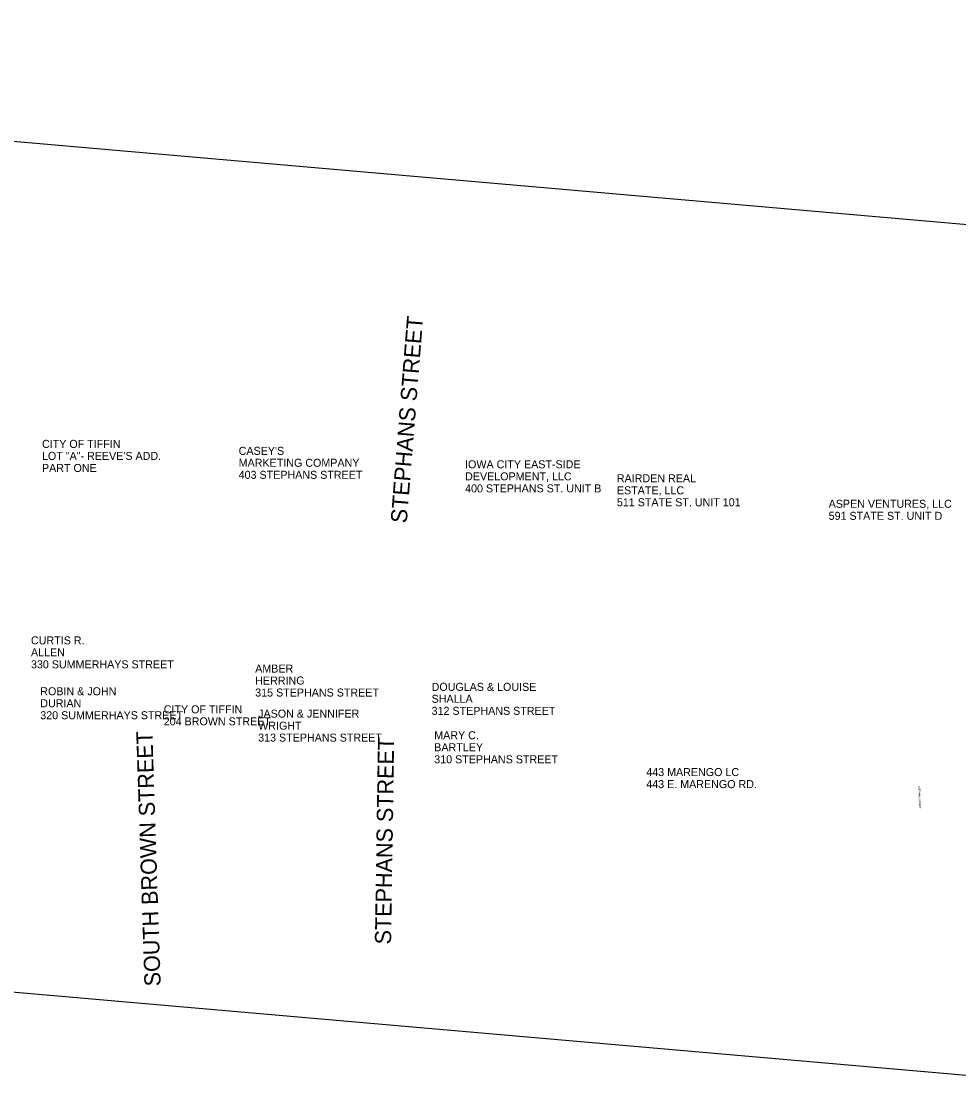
# Model space of a CAD drawing. Extents: x 20499598 to 20505777, y 7953097 to 7954577.
# Drawn here: x 20501318 to 20502423, y 7953308 to 7954577 of the extents above; entities that cross this region are included whole.
import ezdxf

# ---------------------------------------------------------------- set-up
doc = ezdxf.new("R2010")
doc.units = 0
for name, color, linetype in [('Default', 7, 'Continuous'), ('DisROW Property Lines', 7, 'Continuous'), ('NamedBoundary', 7, 'Continuous'), ('Text', 7, 'Continuous')]:
    doc.layers.add(name, color=color, linetype=linetype)

msp = doc.modelspace()

# ---------------------------------------------------------------- linework, layer by layer
at = {"layer": 'NamedBoundary'}
msp.add_lwpolyline([(20499685.1, 7954577.3), (20499598.1, 7953581.1), (20502721.2, 7953308.4), (20502808.2, 7954304.6)], close=True, dxfattribs=at)

# ---------------------------------------------------------------- texts
at = {"layer": 'Default'}
for p in [(20502376, 7953675), (20502376, 7953674.9)]:
    msp.add_text('STEPHANS STREET', height=2, rotation=271.5172, dxfattribs=at).set_placement(p)
at = {"layer": 'DisROW Property Lines'}
for s, height, p in [('CITY OF TIFFIN', 9.449, (20501341.8, 7954074)), ('LOT "A"- REEVE\'S ADD.', 9.449, (20501341.8, 7954059.8)), ("CASEY'S", 9.45, (20501573.9, 7954065.8)), ('PART ONE', 9.45, (20501341.8, 7954045.6)), ('MARKETING COMPANY', 9.449, (20501573.9, 7954051.7)), ('IOWA CITY EAST-SIDE', 9.449, (20501841.1, 7954049.9)), ('403 STEPHANS STREET', 9.449, (20501573.9, 7954037.5)), ('DEVELOPMENT, LLC', 9.449, (20501841.1, 7954035.7)), ('RAIRDEN REAL ', 9.449, (20502020.2, 7954033.4)), ('400 STEPHANS ST. UNIT B', 9.449, (20501841.1, 7954021.5)), ('ESTATE, LLC', 9.449, (20502020.2, 7954019.2)), ('511 STATE ST. UNIT 101', 9.449, (20502020.2, 7954005.1)), ('ASPEN VENTURES, LLC', 9.449, (20502270.1, 7954003.3)), ('591 STATE ST. UNIT D', 9.449, (20502270.1, 7953989.1)), ('CURTIS R.', 9.45, (20501328.8, 7953842.1)), ('ALLEN', 9.45, (20501328.8, 7953827.9)), ('330 SUMMERHAYS STREET', 9.449, (20501328.8, 7953813.8)), ('AMBER', 9.45, (20501593.4, 7953808.8)), ('HERRING', 9.45, (20501593.4, 7953794.7)), ('ROBIN & JOHN', 9.449, (20501339.8, 7953782)), ('315 STEPHANS STREET', 9.449, (20501593.4, 7953780.5)), ('DOUGLAS & LOUISE', 9.449, (20501801.6, 7953787.2)), ('DURIAN', 9.45, (20501339.8, 7953767.8)), ('SHALLA', 9.45, (20501801.6, 7953773.1)), ('320 SUMMERHAYS STREET', 9.449, (20501339.8, 7953753.7)), ('CITY OF TIFFIN', 9.449, (20501485.5, 7953760.7)), ('JASON & JENNIFER', 9.449, (20501596.9, 7953755.6)), ('312 STEPHANS STREET', 9.449, (20501801.6, 7953758.9)), ('204 BROWN STREET', 9.449, (20501485.5, 7953746.5)), ('WRIGHT', 9.45, (20501596.9, 7953741.4)), ('313 STEPHANS STREET', 9.449, (20501596.9, 7953727.3)), ('MARY C.', 9.45, (20501804.7, 7953730.1)), ('BARTLEY', 9.45, (20501804.7, 7953715.9)), ('310 STEPHANS STREET', 9.449, (20501804.7, 7953701.7)), ('443 MARENGO LC', 9.449, (20502054.9, 7953686.6)), ('443 E. MARENGO RD.', 9.449, (20502054.9, 7953672.4))]:
    msp.add_text(s, height=height, dxfattribs=at).set_placement(p)
at = {"layer": 'Text'}
for s, rotation, p in [('STEPHANS STREET', 85.4303, (20501772.2, 7953984.6)), ('SOUTH BROWN STREET', 91.8771, (20501481.9, 7953438.7)), ('STEPHANS STREET', 89.139, (20501753.7, 7953487.8))]:
    msp.add_text(s, height=19.051, rotation=rotation, dxfattribs=at).set_placement(p)

doc.saveas('drawing.dxf')
